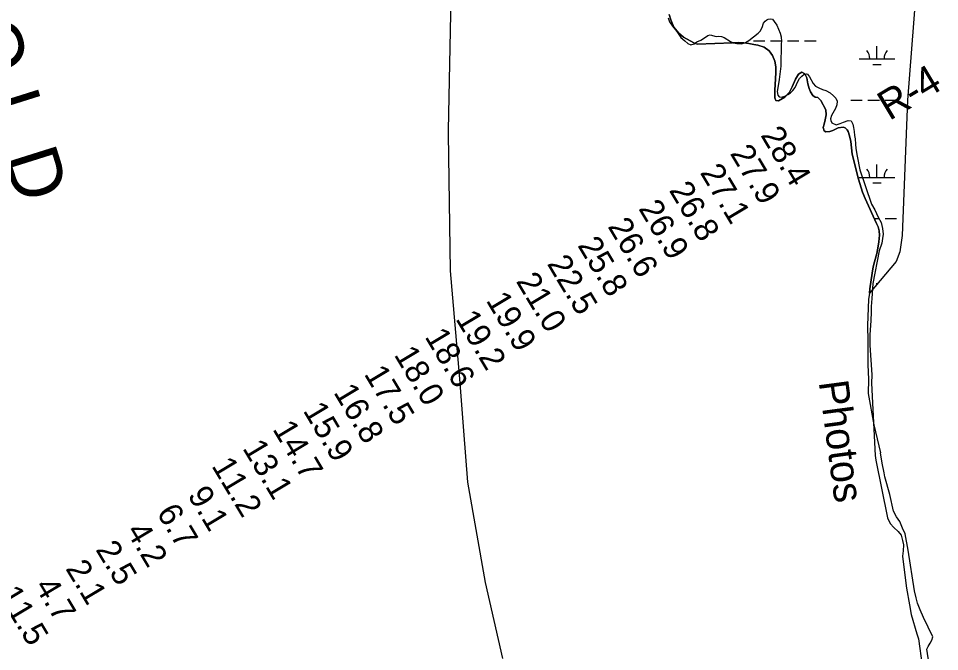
# Model space of a CAD drawing. Extents: x 3161564 to 3199464, y 849354 to 874788.
# Drawn here: x 3176490 to 3179078, y 857334 to 859111 of the extents above; entities that cross this region are included whole.
import ezdxf

# ---------------------------------------------------------------- set-up
doc = ezdxf.new("R2010")
doc.units = 0
for name, color, linetype in [('V-RIVR-IDEN', 7, 'Continuous'), ('V-RIVR-RANG', 7, 'Continuous'), ('V-RIVR-RANG-IDEN', 7, 'Continuous'), ('V-ROAD-CNTR', 7, 'Continuous'), ('V-SITE-VEGE', 7, 'Continuous'), ('V-TOPO-BNDY', 7, 'Continuous'), ('V-TOPO-SHOR', 7, 'Continuous'), ('V-WETL-SWMP', 7, 'Continuous')]:
    doc.layers.add(name, color=color, linetype=linetype)

msp = doc.modelspace()

# ---------------------------------------------------------------- linework, layer by layer
at = {"layer": 'V-ROAD-CNTR'}
msp.add_spline([(3176879.1, 855651.9), (3176902.3, 855659.1), (3176934.1, 855667), (3176983.4, 855657.7), (3177040.7, 855639.1), (3177110.5, 855613.6), (3177170.6, 855601.8), (3177236.8, 855586.9), (3177274.8, 855573.5), (3177317.4, 855579.8), (3177362.6, 855595.7), (3177412, 855643.1), (3177451.7, 855679.2), (3177476.7, 855705.8), (3177478.3, 855737), (3177464.2, 855782.3), (3177430.8, 855833.4), (3177373, 855887.8), (3177287.8, 855954.8), (3177219.8, 855998.4), (3177153, 856039.4), (3177089.3, 856079.2), (3177023.4, 856134.3), (3176966.6, 856207.9), (3176895.2, 856290.1), (3176782.2, 856425.1), (3176693.2, 856545.3), (3176615.2, 856622.6), (3176543.9, 856726.5), (3176474.4, 856784.2), (3176414.4, 856823.6), (3176395.9, 856828), (3176350.8, 856806.2), (3176279.1, 856754.7), (3176211.6, 856707.4), (3176172.3, 856696.1), (3176141.1, 856702), (3176111.7, 856719.6), (3176032.6, 856777.4), (3175933.6, 856857.4), (3175839, 856930.3), (3175807.1, 856951.5), (3175770.1, 856958.7), (3175787.1, 856991.4), (3175795.1, 857040.7), (3175799.5, 857113.7), (3175810.8, 857206.9), (3175813.7, 857287.4), (3175807.8, 857386.8), (3175805.7, 857497.9), (3175801.9, 857543.6), (3175783.5, 857620.5), (3175760.2, 857716.1), (3175755.3, 857765.5), (3175754.5, 857815.6), (3175751.7, 857884.3), (3175756.3, 858015.5), (3175754.9, 858158.6), (3175753.1, 858270.8), (3175748.6, 858321.7), (3175736.5, 858372), (3175677.2, 858555.5), (3175602.2, 858747.1), (3175558.2, 858866.9), (3175502.5, 858986.2), (3175436.3, 859092.6), (3175371.2, 859185.1), (3175300.7, 859261.6), (3175219.1, 859367.2), (3175166.2, 859443.7), (3175175.3, 859507.1), (3175222, 859537.9), (3175285.3, 859568.3), (3175321.2, 859607.5), (3175310.3, 859667.2), (3175262.4, 859798.6), (3175224.6, 859877.9), (3175174.7, 859982), (3175144.8, 860115.4), (3175122.6, 860284.8), (3175088.4, 860568.6), (3175086.3, 860704.5), (3175072.2, 860854.5), (3175052.5, 860999.9), (3175047.5, 861166.8), (3175053.2, 861343.7), (3175066.7, 861550.4), (3175065.5, 861662.5), (3175040.2, 861767.8), (3175017.8, 861884.2), (3175008.4, 862033.9), (3174979.6, 862160.3), (3174952.1, 862274.6), (3174921.6, 862422.8), (3174897, 862525.5), (3174861.7, 862663.2), (3174841.1, 862738)], degree=3, dxfattribs=at)
at = {"layer": 'V-SITE-VEGE'}
for p, q in [((3178315, 859112.3), (3178319.1, 859101.1)), ((3178583.3, 859097.2), (3178587.3, 859102.8)), ((3178587.3, 859102.8), (3178592.6, 859107.3)), ((3178592.6, 859107.3), (3178596.3, 859109.3)), ((3178596.3, 859109.3), (3178603.5, 859109.5)), ((3178603.5, 859109.5), (3178608.3, 859108.4)), ((3178608.3, 859108.4), (3178613.4, 859102.4)), ((3178319.1, 859101.1), (3178327.2, 859089.2)), ((3178327.2, 859089.2), (3178339.3, 859074.5)), ((3178573.3, 859074.8), (3178579.2, 859085.9)), ((3178579.2, 859085.9), (3178583.3, 859097.2)), ((3178613.4, 859102.4), (3178620.2, 859092)), ((3178620.2, 859092), (3178624.8, 859080.7)), ((3178624.8, 859080.7), (3178629.4, 859070)), ((3178339.3, 859074.5), (3178351.1, 859057.8)), ((3178351.1, 859057.8), (3178362.3, 859047.7)), ((3178407, 859049.6), (3178417.2, 859056.1)), ((3178417.2, 859056.1), (3178426.3, 859062.6)), ((3178426.3, 859062.6), (3178432.9, 859064.6)), ((3178432.9, 859064.6), (3178450, 859060.2)), ((3178450, 859060.2), (3178455.9, 859061.4)), ((3178455.9, 859061.4), (3178464.8, 859059.8)), ((3178464.8, 859059.8), (3178472.7, 859057.1)), ((3178472.7, 859057.1), (3178489.9, 859046)), ((3178542.3, 859048.6), (3178568.1, 859069.7)), ((3178568.1, 859069.7), (3178573.3, 859074.8)), ((3178629.4, 859070), (3178632.6, 859059.1)), ((3178632.6, 859059.1), (3178633.4, 859045.9)), ((3178362.3, 859047.7), (3178370.2, 859040.9)), ((3178370.2, 859040.9), (3178378.8, 859037)), ((3178378.8, 859037), (3178388.4, 859039.6)), ((3178388.4, 859039.6), (3178395.4, 859044.9)), ((3178395.4, 859044.9), (3178407, 859049.6)), ((3178489.9, 859046), (3178498.1, 859042.2)), ((3178498.1, 859042.2), (3178507.7, 859040.5)), ((3178507.7, 859040.5), (3178520.8, 859040)), ((3178520.8, 859040), (3178532.5, 859043.2)), ((3178532.5, 859043.2), (3178542.3, 859048.6)), ((3178633.1, 859040.1), (3178631.8, 858977.2)), ((3178633.4, 859045.9), (3178633.1, 859040.1)), ((3178631.8, 858977.2), (3178627.4, 858939.1)), ((3178684.5, 858942.7), (3178690.3, 858949.1)), ((3178690.3, 858949.1), (3178697.7, 858954)), ((3178697.7, 858954), (3178703.9, 858955.5)), ((3178703.9, 858955.5), (3178706.7, 858954.1)), ((3178706.7, 858954.1), (3178712.5, 858946.7)), ((3178627.4, 858939.1), (3178624, 858921.4)), ((3178671.9, 858916.7), (3178675.6, 858925.5)), ((3178675.6, 858925.5), (3178679.5, 858933.5)), ((3178679.5, 858933.5), (3178684.5, 858942.7)), ((3178712.5, 858946.7), (3178722.5, 858928.5)), ((3178722.5, 858928.5), (3178729.4, 858920.3)), ((3178624, 858921.4), (3178621.7, 858905.6)), ((3178621.7, 858905.6), (3178623.2, 858895.3)), ((3178642.6, 858893.1), (3178651.2, 858897.2)), ((3178651.2, 858897.2), (3178658.7, 858902.4)), ((3178658.7, 858902.4), (3178665.7, 858908.8)), ((3178665.7, 858908.8), (3178671.9, 858916.7)), ((3178729.4, 858920.3), (3178738.4, 858915.8)), ((3178738.4, 858915.8), (3178749.1, 858911.8)), ((3178749.1, 858911.8), (3178757.9, 858909)), ((3178757.9, 858909), (3178770.3, 858902.5)), ((3178770.3, 858902.5), (3178780, 858894)), ((3178623.2, 858895.3), (3178627.3, 858891)), ((3178627.3, 858891), (3178633.7, 858890.2)), ((3178633.7, 858890.2), (3178642.6, 858893.1)), ((3178780, 858894), (3178786.4, 858886.8)), ((3178786.4, 858886.8), (3178789.9, 858878.6)), ((3178789.9, 858878.6), (3178788.8, 858868)), ((3178785.3, 858858.1), (3178773.6, 858838.2)), ((3178788.8, 858868), (3178785.3, 858858.1)), ((3178773.6, 858838.2), (3178770.8, 858828.6)), ((3178770.8, 858828.6), (3178771.7, 858824.2)), ((3178771.7, 858824.2), (3178775, 858817.7)), ((3178798.4, 858815.9), (3178807.5, 858819.6)), ((3178807.5, 858819.6), (3178821.1, 858824.2)), ((3178821.1, 858824.2), (3178829.1, 858823.1)), ((3178829.1, 858823.1), (3178834.4, 858813.9)), ((3178775, 858817.7), (3178787.3, 858812)), ((3178787.3, 858812), (3178798.4, 858815.9)), ((3178834.4, 858813.9), (3178836.1, 858804.6)), ((3178836.1, 858804.6), (3178837.4, 858793.6)), ((3178837.4, 858793.6), (3178839, 858782.3)), ((3178839, 858782.3), (3178840.6, 858772.5)), ((3178840.6, 858772.5), (3178841.2, 858757.5)), ((3178841.2, 858757.5), (3178842.1, 858745.4)), ((3178842.1, 858745.4), (3178845.7, 858724.2)), ((3178845.7, 858724.2), (3178853.7, 858686.1)), ((3178853.7, 858686.1), (3178886.5, 858589.2)), ((3178886.5, 858589.2), (3178895.3, 858573.7)), ((3178895.3, 858573.7), (3178904.9, 858553.1)), ((3178904.9, 858553.1), (3178913.6, 858537.8)), ((3178913.6, 858537.8), (3178917.7, 858520.9)), ((3178917.7, 858520.9), (3178919, 858505.4)), ((3178917.7, 858492.8), (3178915.5, 858480)), ((3178919, 858505.4), (3178917.7, 858492.8)), ((3178908, 858458.2), (3178890.3, 858367.2)), ((3178915.5, 858480), (3178908, 858458.2)), ((3178890.3, 858367.2), (3178887.7, 858324.4)), ((3178885.8, 858302.7), (3178885.5, 858287.1)), ((3178887.7, 858324.4), (3178885.8, 858302.7)), ((3178885.5, 858287.1), (3178884.3, 858262.4)), ((3178884.3, 858262.4), (3178881.5, 858223.4)), ((3178881.5, 858223.4), (3178881.4, 858193.8)), ((3178881.4, 858193.8), (3178887, 858110.5)), ((3178887, 858110.5), (3178886.4, 858087.1)), ((3178886.4, 858087.1), (3178896.6, 857883.7)), ((3178896.6, 857883.7), (3178898.1, 857871.3)), ((3178898.1, 857871.3), (3178931.1, 857709.2)), ((3178931.1, 857709.2), (3178939, 857693.1)), ((3178939, 857693.1), (3178948.9, 857682.1)), ((3178948.9, 857682.1), (3178961.7, 857671)), ((3178961.7, 857671), (3178969.8, 857660)), ((3178969.8, 857660), (3178973.2, 857645.7)), ((3178973.2, 857645.7), (3178975.8, 857633.3)), ((3178975.8, 857633.3), (3178975.4, 857616.5)), ((3178975.4, 857616.5), (3178973.9, 857601.2)), ((3178973.9, 857601.2), (3178974.3, 857593)), ((3178974.3, 857593), (3178984.7, 857511.6)), ((3178984.7, 857511.6), (3178993, 857464.4)), ((3178993, 857464.4), (3178998.2, 857437.8)), ((3178998.2, 857437.8), (3179013.5, 857383.7)), ((3179013.5, 857383.7), (3179018.5, 857369.2)), ((3179018.5, 857369.2), (3179028.7, 857294.2))]:
    msp.add_line(p, q, dxfattribs=at)
at = {"layer": 'V-TOPO-BNDY'}
for p, q in [((3177698.7, 858796.9), (3177706.7, 859204.4)), ((3177698.6, 858786.7), (3177698.7, 858796.9)), ((3177704, 858401.9), (3177698.6, 858786.7)), ((3177730.4, 858099.6), (3177704, 858401.9)), ((3177741.6, 857953.4), (3177730.4, 858099.6)), ((3177752.6, 857808.8), (3177741.6, 857953.4)), ((3177802.6, 857527.1), (3177752.6, 857808.8)), ((3177851.3, 857313.7), (3177802.6, 857527.1))]:
    msp.add_line(p, q, dxfattribs=at)
at = {"layer": 'V-TOPO-SHOR'}
for points in [[(3178318.5, 859122), (3178322.5, 859106.9), (3178331.1, 859086.7), (3178344.1, 859070.3), (3178357.9, 859058.4), (3178387.3, 859042.8), (3178396.5, 859038.6), (3178495.7, 859042.7), (3178512.9, 859043.1), (3178528.1, 859042.1), (3178541.8, 859040.5), (3178555.9, 859037.4), (3178567.1, 859036.3), (3178584.8, 859030.3), (3178598.9, 859019.7), (3178608.4, 859007.2), (3178615.2, 858990.7), (3178617.6, 858974.7), (3178617.6, 858958.8), (3178615.8, 858924.8), (3178614.9, 858910.4), (3178614.5, 858899.4), (3178614.5, 858887.8), (3178617.4, 858880.3), (3178625.6, 858879.8), (3178642.5, 858889.8), (3178656.2, 858904.3), (3178663.6, 858919.3), (3178672.9, 858940.1), (3178681.7, 858954.9), (3178690.8, 858960.1), (3178698.8, 858955.6), (3178704.6, 858944.6), (3178707.5, 858927), (3178711.3, 858914.2), (3178715.5, 858904.4), (3178721.3, 858894.7), (3178728.1, 858889.7), (3178736.1, 858888.6), (3178744.1, 858880.9), (3178757.9, 858854.1), (3178759.1, 858840.3), (3178756.6, 858826.1), (3178753.1, 858814.2), (3178750.9, 858804.7), (3178753.1, 858795.7), (3178758.1, 858792.4), (3178769.3, 858793.7), (3178777.6, 858796.3), (3178786.7, 858800.9), (3178793.1, 858804), (3178806.5, 858806), (3178812.7, 858803.5), (3178817.6, 858798.4), (3178821.3, 858793.2), (3178825, 858781.3), (3178828.1, 858765.4)], [(3178828.1, 858765.4), (3178832.3, 858730), (3178850.2, 858659.4), (3178861.3, 858622.8), (3178868.3, 858605.4), (3178900.7, 858535.6), (3178904.7, 858525.6), (3178908.2, 858514.6), (3178909.2, 858502.1), (3178906.8, 858483.6), (3178904.9, 858471.2), (3178901.4, 858451.1), (3178895, 858427.8), (3178891.4, 858413.9), (3178888.4, 858395.5), (3178882, 858351.7), (3178880.4, 858339.4)], [(3178880.4, 858339.4), (3178878.3, 858322.2), (3178875.3, 858249.9), (3178876, 858203.6), (3178875.7, 858172.7), (3178875.7, 858138.6), (3178877.8, 858098.4), (3178876.8, 858058.4), (3178892.5, 857970.4), (3178911.2, 857891.5)], [(3178921.5, 857835.7), (3178916.4, 857862.5), (3178911.2, 857891.5)], [(3179053.5, 857268.1), (3179042.2, 857340.4), (3179045.2, 857347.7), (3179051.5, 857357), (3179056.2, 857365.2), (3179058.4, 857374.5), (3179032, 857429.3), (3179022.9, 857451.1), (3179015.5, 857469.7), (3179011.5, 857484.3), (3179007.5, 857504.2), (3178989.5, 857617.9), (3178980.7, 857663.6), (3178973.6, 857680.3), (3178965.6, 857698.3), (3178956.6, 857711.4), (3178947.8, 857727.4), (3178937.7, 857774.9), (3178924, 857824.4), (3178921.5, 857835.7)]]:
    msp.add_lwpolyline(points, dxfattribs=at)
at = {"layer": 'V-WETL-SWMP'}
for p, q in [((3179019.5, 859286.4), (3178987.5, 858881.9)), ((3178322.5, 859106.9), (3178318.5, 859122)), ((3178331.1, 859086.7), (3178322.5, 859106.9)), ((3178344.1, 859070.3), (3178331.1, 859086.7)), ((3178357.9, 859058.4), (3178344.1, 859070.3)), ((3178387.4, 859042.8), (3178357.9, 859058.4)), ((3178396.5, 859038.6), (3178387.4, 859042.8)), ((3178495.7, 859042.7), (3178396.5, 859038.6)), ((3178512.9, 859043.1), (3178495.7, 859042.7)), ((3178528.1, 859042.1), (3178512.9, 859043.1)), ((3178541.8, 859040.5), (3178528.1, 859042.1)), ((3178555.9, 859037.4), (3178541.8, 859040.5)), ((3178554.5, 859048), (3178586.5, 859048)), ((3178567.1, 859036.3), (3178555.9, 859037.4)), ((3178584.8, 859030.3), (3178567.1, 859036.3)), ((3178598.9, 859019.7), (3178584.8, 859030.3)), ((3178602.5, 859048), (3178634.5, 859048)), ((3178650.5, 859048), (3178682.5, 859048)), ((3178698.5, 859048), (3178730.5, 859048)), ((3178901.8, 858997.3), (3178901.8, 859033.3)), ((3178608.4, 859007.2), (3178598.9, 859019.7)), ((3178615.2, 858990.7), (3178608.4, 859007.2)), ((3178617.6, 858974.7), (3178615.2, 858990.7)), ((3178617.6, 858958.8), (3178617.6, 858974.7)), ((3178851.8, 858997.3), (3178951.8, 858997.3)), ((3178889.8, 858981.8), (3178913.8, 858981.8)), ((3178615.8, 858924.8), (3178617.6, 858958.8)), ((3178681.8, 858954.9), (3178672.9, 858940.1)), ((3178690.8, 858960.1), (3178681.8, 858954.9)), ((3178698.8, 858955.6), (3178690.8, 858960.1)), ((3178704.6, 858944.6), (3178698.8, 858955.6)), ((3178614.9, 858910.4), (3178615.8, 858924.8)), ((3178672.9, 858940.1), (3178663.6, 858919.3)), ((3178707.5, 858927), (3178704.6, 858944.6)), ((3178711.3, 858914.2), (3178707.5, 858927)), ((3178614.5, 858899.4), (3178614.9, 858910.4)), ((3178614.5, 858887.8), (3178614.5, 858899.4)), ((3178656.2, 858904.3), (3178642.5, 858889.8)), ((3178663.6, 858919.3), (3178656.2, 858904.3)), ((3178715.5, 858904.4), (3178711.3, 858914.2)), ((3178721.3, 858894.7), (3178715.5, 858904.4)), ((3178617.4, 858880.3), (3178614.5, 858887.8)), ((3178625.6, 858879.8), (3178617.4, 858880.3)), ((3178642.5, 858889.8), (3178625.6, 858879.8)), ((3178728.1, 858889.7), (3178721.3, 858894.7)), ((3178736.1, 858888.6), (3178728.1, 858889.7)), ((3178744.1, 858880.9), (3178736.1, 858888.6)), ((3178757.9, 858854.1), (3178744.1, 858880.9)), ((3178828.4, 858881.8), (3178860.4, 858881.8)), ((3178876.4, 858881.8), (3178908.4, 858881.8)), ((3178924.4, 858881.8), (3178956.4, 858881.8)), ((3178987.5, 858881.9), (3178972.4, 858501.5)), ((3178759.1, 858840.3), (3178757.9, 858854.1)), ((3178753.1, 858814.2), (3178756.6, 858826.1)), ((3178756.6, 858826.1), (3178759.1, 858840.3)), ((3178750.9, 858804.7), (3178753.1, 858814.2)), ((3178753.1, 858795.7), (3178750.9, 858804.7)), ((3178758.1, 858792.4), (3178753.1, 858795.7)), ((3178769.3, 858793.7), (3178758.1, 858792.4)), ((3178777.6, 858796.3), (3178769.3, 858793.7)), ((3178786.7, 858800.9), (3178777.6, 858796.3)), ((3178793.1, 858804), (3178786.7, 858800.9)), ((3178806.5, 858806), (3178793.1, 858804)), ((3178812.7, 858803.5), (3178806.5, 858806)), ((3178817.6, 858798.4), (3178812.7, 858803.5)), ((3178821.3, 858793.2), (3178817.6, 858798.4)), ((3178825, 858781.3), (3178821.3, 858793.2)), ((3178828.1, 858765.4), (3178825, 858781.3)), ((3178832.3, 858730), (3178828.1, 858765.4)), ((3178850.2, 858659.4), (3178832.3, 858730)), ((3178901.8, 858664.6), (3178901.8, 858700.6)), ((3178851.8, 858664.6), (3178951.8, 858664.6)), ((3178861.3, 858622.8), (3178850.2, 858659.4)), ((3178889.8, 858649.1), (3178913.8, 858649.1)), ((3178868.3, 858605.4), (3178861.3, 858622.8)), ((3178900.7, 858535.6), (3178868.3, 858605.4)), ((3178894.4, 858549.1), (3178908.4, 858549.1)), ((3178904.7, 858525.6), (3178900.7, 858535.6)), ((3178924.4, 858549.1), (3178956.4, 858549.1)), ((3178908.2, 858514.6), (3178904.7, 858525.6)), ((3178909.2, 858502.1), (3178908.2, 858514.6)), ((3178904.9, 858471.2), (3178906.8, 858483.6)), ((3178906.8, 858483.6), (3178909.2, 858502.1)), ((3178972.4, 858501.5), (3178965.8, 858456.1)), ((3178901.4, 858451.1), (3178904.9, 858471.2)), ((3178965.8, 858456.1), (3178955.8, 858428.3)), ((3178895, 858427.8), (3178901.4, 858451.1)), ((3178955.8, 858428.3), (3178880.4, 858339.4)), ((3178888.5, 858395.5), (3178891.4, 858413.9)), ((3178891.4, 858413.9), (3178895, 858427.8)), ((3178882, 858351.7), (3178888.5, 858395.5)), ((3178901.8, 858364.6), (3178901.8, 858367.9)), ((3178880.4, 858339.4), (3178882, 858351.7))]:
    msp.add_line(p, q, dxfattribs=at)
for centre, start, end in [((3178846.5, 858997.7), 359.2282, 40.7718), ((3178957, 858997.7), 139.2282, 180.7718), ((3178846.5, 858665.1), 359.2282, 40.7718), ((3178957, 858665.1), 139.2282, 180.7718), ((3178846.5, 858332.4), 12.4467, 14.4097)]:
    msp.add_arc(centre, 35.2, start, end, dxfattribs=at)

# ---------------------------------------------------------------- texts
at = {"layer": 'V-RIVR-IDEN'}
for s, height, rotation, p in [('O L D', 150, 287.4555, (3176334.2, 859083.7)), ('Photos', 83, 277.5922, (3178738, 858090.5))]:
    msp.add_text(s, height=height, rotation=rotation, dxfattribs=at).set_placement(p)
at = {"layer": 'V-RIVR-RANG'}
for s, p in [('28.4', (3178573.4, 858783.4)), ('27.9', (3178487.6, 858732.1)), ('27.1', (3178403.3, 858678.2)), ('26.8', (3178316.4, 858628.7)), ('26.9', (3178230.6, 858577.3)), ('26.6', (3178144.1, 858527.1)), ('25.8', (3178059.4, 858473.9)), ('22.5', (3177973.7, 858422.4)), ('21.0', (3177886.5, 858373.3)), ('19.9', (3177802.2, 858319.4)), ('19.2', (3177716.7, 858267.6)), ('18.6', (3177630.1, 858217.6)), ('18.0', (3177543.8, 858167)), ('17.5', (3177459.7, 858112.9)), ('16.8', (3177374, 858061.3)), ('15.9', (3177288.2, 858010)), ('14.7', (3177202.6, 857958.2)), ('13.1', (3177118.2, 857904.6)), ('11.2', (3177031.3, 857855)), ('9.1', (3176963.9, 857772.9)), ('6.7', (3176877, 857723.4)), ('4.2', (3176791.4, 857671.8)), ('2.5', (3176705.7, 857620.2)), ('2.1', (3176621.2, 857566.6)), ('4.7', (3176534.3, 857517.1)), ('11.5', (3176431.6, 857494))]:
    msp.add_text(s, height=67, rotation=300.9083, dxfattribs=at).set_placement(p)
at = {"layer": 'V-RIVR-RANG-IDEN'}
msp.add_text('R-4', height=83, rotation=31.0485, dxfattribs=at).set_placement((3178936.4, 858822.4))

doc.saveas('drawing.dxf')
